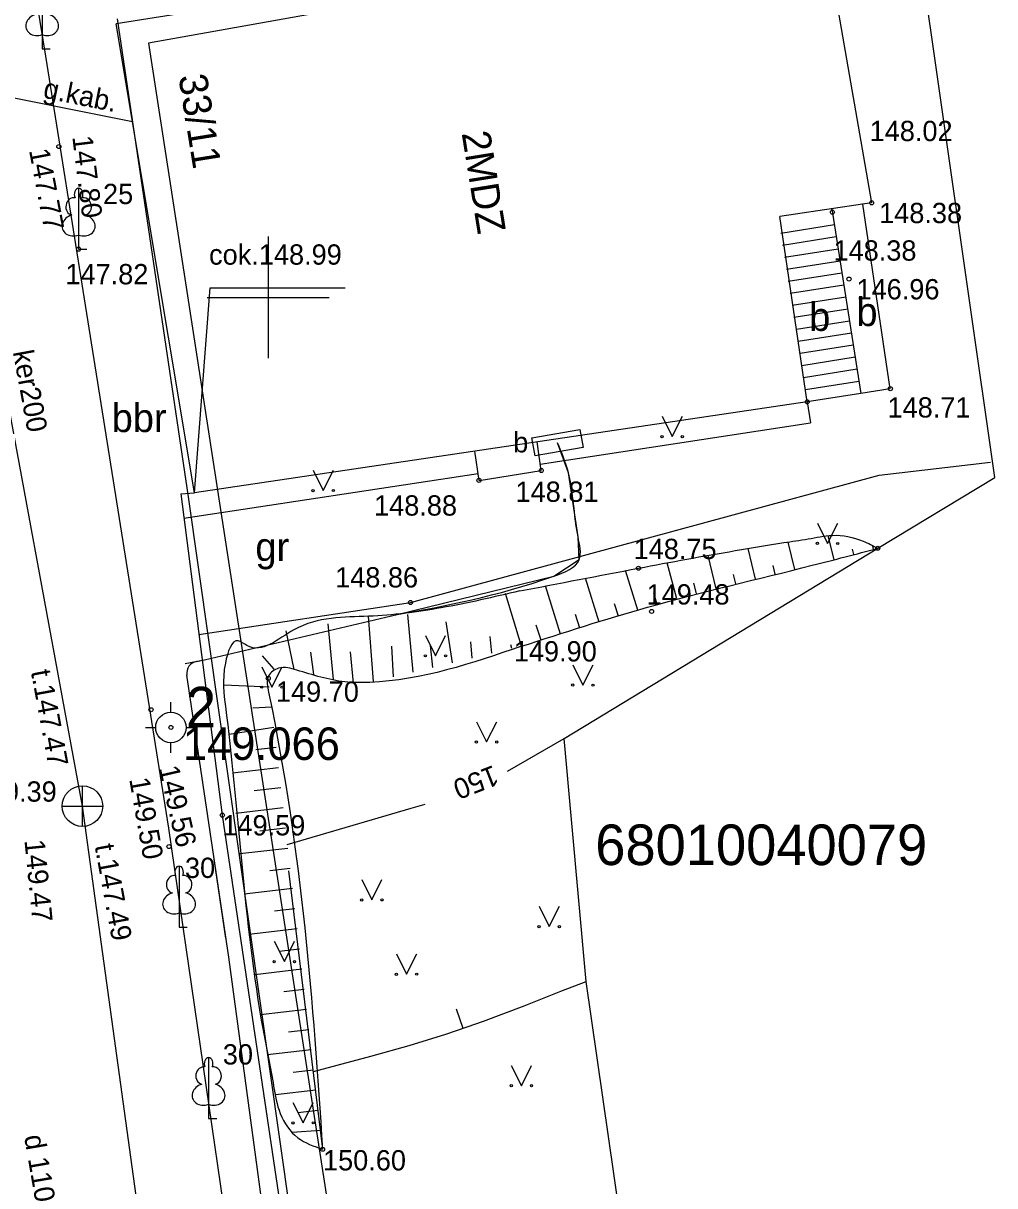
# Model space of a CAD drawing. Extents: x 728710 to 728960, y 272811 to 273475.
# Drawn here: x 728843.96 to 728867.91, y 272928.12 to 272956.75 of the extents above; entities that cross this region are included whole.
import ezdxf

# ---------------------------------------------------------------- set-up
doc = ezdxf.new("R2010")
doc.units = 0
for name, color, linetype in [('Level 10', 7, 'Continuous'), ('Level 12', 7, 'Continuous'), ('Level 15', 7, 'Continuous'), ('Level 23', 7, 'Continuous'), ('Level 29', 7, 'Continuous'), ('Level 3', 7, 'Continuous'), ('Level 30', 7, 'Continuous'), ('Level 34', 7, 'Continuous'), ('Level 36', 7, 'Continuous'), ('Level 4', 7, 'Continuous'), ('Level 48', 7, 'Continuous'), ('Level 50', 7, 'Continuous'), ('Level 51', 7, 'Continuous'), ('Level 55', 7, 'Continuous'), ('Level 56', 7, 'Continuous'), ('Level 57', 7, 'Continuous'), ('Level 58', 7, 'Continuous'), ('Level 59', 7, 'Continuous'), ('Level 6', 7, 'Continuous'), ('Level 60', 7, 'Continuous'), ('Level 62', 7, 'Continuous'), ('Level 63', 7, 'Continuous'), ('Level 9', 7, 'Continuous'), ('RAMI_UZMR_####_####_#', 7, 'Continuous'), ('RELJ_AATZ_####_TKST_#', 7, 'Continuous'), ('RELJ_NOGA_####_####_#', 7, 'Continuous'), ('ROBZ_ELEM_####_####_#', 7, 'Continuous'), ('ROBZ_KADS_####_TKST_#', 7, 'Continuous'), ('ROBZ_UZMR_####_####_#', 7, 'Continuous'), ('SAKT_VADV_PKAB_TKST_#', 7, 'Continuous'), ('TERT_ELEM_####_####_#', 7, 'Continuous'), ('TERT_KONT_####_####_#', 7, 'Continuous')]:
    doc.layers.add(name, color=color, linetype=linetype)

msp = doc.modelspace()

# ---------------------------------------------------------------- linework, layer by layer
at = {"layer": 'Level 10'}
for p, q in [((728850, 272951.5), (728850, 272950)), ((728848.5, 272950), (728850, 272950)), ((728850, 272950), (728850, 272948.5)), ((728850, 272950), (728851.5, 272950)), ((728847.603, 272939.781), (728847.603, 272940.031)), ((728846.978, 272939.406), (728847.228, 272939.406)), ((728847.978, 272939.406), (728848.228, 272939.406)), ((728847.603, 272938.781), (728847.603, 272939.031))]:
    msp.add_line(p, q, dxfattribs=at)
for radius in [0.375, 0.05]:
    msp.add_circle((728847.603, 272939.406), radius, dxfattribs=at)
at = {"layer": 'Level 12'}
for p, q in [((728862.984, 272943.296), (728862.82, 272943.972)), ((728863.954, 272943.541), (728863.802, 272944.123)), ((728864.922, 272943.793), (728864.899, 272943.881)), ((728861.041, 272942.825), (728860.842, 272943.643)), ((728862.013, 272943.061), (728861.83, 272943.814)), ((728864.438, 272943.667), (728864.403, 272943.801)), ((728859.113, 272942.294), (728858.811, 272943.269)), ((728860.073, 272942.575), (728859.837, 272943.462)), ((728862.498, 272943.179), (728862.446, 272943.394)), ((728858.158, 272941.998), (728857.823, 272943.08)), ((728861.527, 272942.943), (728861.469, 272943.178)), ((728856.247, 272941.407), (728855.846, 272942.702)), ((728857.202, 272941.703), (728856.835, 272942.891)), ((728859.591, 272942.439), (728859.509, 272942.717)), ((728860.556, 272942.703), (728860.488, 272942.958)), ((728858.635, 272942.146), (728858.54, 272942.455)), ((728852.599, 272940.537), (728852.477, 272942.144)), ((728853.572, 272940.769), (728853.44, 272942.19)), ((728857.68, 272941.851), (728857.575, 272942.191)), ((728851.612, 272940.588), (728851.479, 272941.96)), ((728854.545, 272941.001), (728854.39, 272942.006)), ((728856.725, 272941.555), (728856.609, 272941.927)), ((728850.642, 272940.831), (728850.447, 272941.788)), ((728855.517, 272941.233), (728855.473, 272941.65)), ((728851.128, 272940.713), (728851.054, 272941.261)), ((728852.104, 272940.5), (728852.029, 272941.272)), ((728853.086, 272940.653), (728853.05, 272941.41)), ((728854.058, 272940.885), (728854, 272941.421)), ((728855.031, 272941.117), (728854.997, 272941.519)), ((728856.004, 272941.349), (728855.983, 272941.444)), ((728850.148, 272940.839), (728849.862, 272941.169)), ((728850.024, 272940.402), (728848.911, 272940.447)), ((728850.081, 272939.905), (728849.626, 272939.878)), ((728850.139, 272939.408), (728849.036, 272939.236)), ((728850.196, 272938.912), (728849.699, 272938.854)), ((728850.254, 272938.415), (728849.118, 272938.283)), ((728850.311, 272937.918), (728849.659, 272937.843)), ((728850.369, 272937.422), (728849.206, 272937.287)), ((728850.426, 272936.925), (728849.797, 272936.852)), ((728850.484, 272936.428), (728849.302, 272936.291)), ((728850.541, 272935.931), (728850.044, 272935.874)), ((728850.599, 272935.435), (728849.408, 272935.297)), ((728850.656, 272934.938), (728850.159, 272934.881)), ((728850.714, 272934.441), (728849.527, 272934.304)), ((728850.771, 272933.945), (728850.274, 272933.887)), ((728850.829, 272933.448), (728849.669, 272933.314)), ((728850.886, 272932.951), (728850.389, 272932.894)), ((728850.944, 272932.455), (728849.813, 272932.324)), ((728851.001, 272931.958), (728850.504, 272931.901)), ((728851.059, 272931.461), (728849.985, 272931.337)), ((728851.116, 272930.965), (728850.62, 272930.907)), ((728851.174, 272930.468), (728850.18, 272930.353)), ((728851.231, 272929.971), (728850.735, 272929.914)), ((728851.289, 272929.475), (728850.595, 272929.424))]:
    msp.add_line(p, q, dxfattribs=at)
for points in [[(728856.247, 272941.407), (728859.353, 272942.368), (728863.411, 272943.4), (728865.025, 272943.82)], [(728856.247, 272941.407), (728852.507, 272940.515), (728851.889, 272940.53), (728850.706, 272940.818), (728850.259, 272940.864), (728850.011, 272940.679), (728850.011, 272940.273), (728851.342, 272929.014)]]:
    msp.add_spline(points, degree=3, dxfattribs=at)
at = {"layer": 'Level 15'}
msp.add_lwpolyline([(728856.5, 272946.539), (728857.683, 272946.744), (728857.76, 272946.301), (728856.577, 272946.096)], close=True, dxfattribs=at)
at = {"layer": 'Level 23'}
msp.add_lwpolyline([(728849.007, 272911.469), (728845.423, 272937.468), (728840.671, 272963.226)], dxfattribs=at)
at = {"layer": 'Level 29'}
for p, q in [((728845.423, 272936.968), (728845.423, 272937.968)), ((728844.923, 272937.468), (728845.923, 272937.468))]:
    msp.add_line(p, q, dxfattribs=at)
msp.add_circle((728845.423, 272937.468), 0.5, dxfattribs=at)
at = {"layer": 'Level 3'}
for p, q in [((728863.627, 272959.495), (728846.257, 272956.74)), ((728863.627, 272959.495), (728864.872, 272952.33)), ((728848.185, 272945.19), (728846.257, 272956.74)), ((728864.872, 272952.33), (728862.609, 272951.995)), ((728863.286, 272947.428), (728862.609, 272951.995)), ((728863.286, 272947.428), (728848.185, 272945.19))]:
    msp.add_line(p, q, dxfattribs=at)
at = {"layer": 'Level 30'}
for points in [[(728854.901, 272932.029), (728855.308, 272932.171), (728856.31, 272932.552), (728857.21, 272932.906), (728857.836, 272933.151)], [(728851.12, 272930.929), (728851.701, 272931.086), (728852.533, 272931.31), (728853.472, 272931.573), (728854.377, 272931.846), (728854.901, 272932.029)]]:
    msp.add_lwpolyline(points, dxfattribs=at)
at = {"layer": 'Level 34'}
for points in [[(728856.199, 272942.769), (728859.127, 272943.329), (728860.319, 272943.552), (728861.513, 272943.762), (728862.709, 272943.959), (728863.306, 272944.051), (728863.903, 272944.139), (728864.662, 272943.996), (728865.025, 272943.82)], [(728856.199, 272942.769), (728854.268, 272942.352), (728852.477, 272942.144), (728850.634, 272941.81), (728849.478, 272941.421), (728849.262, 272941.54), (728848.947, 272940.993), (728848.947, 272939.921), (728849.876, 272931.948), (728850.135, 272930.573), (728850.299, 272929.893), (728850.73, 272929.3), (728851.342, 272929.014)]]:
    msp.add_spline(points, degree=3, dxfattribs=at)
at = {"layer": 'Level 36'}
for points in [[(728847.955, 272940.979), (728848.43, 272941.072), (728853.176, 272942.187), (728857.037, 272943.133), (728857.668, 272943.54), (728857.638, 272944.102), (728857.402, 272945.676), (728857.13, 272946.42)], [(728848.959, 272934.212), (728848.67, 272936.162)]]:
    msp.add_lwpolyline(points, dxfattribs=at)
at = {"layer": 'Level 4'}
for p, q in [((728856.707, 272945.895), (728863.365, 272946.907)), ((728855.174, 272945.65), (728847.924, 272944.551)), ((728848.291, 272941.698), (728853.509, 272942.484))]:
    msp.add_line(p, q, dxfattribs=at)
for points in [[(728856.484, 272960.622), (728845.294, 272958.672), (728844.766, 272958.358), (728844.393, 272957.882), (728844.309, 272957.202), (728844.514, 272955.94), (728847.548, 272936.925), (728849.888, 272920.816), (728857.475, 272869.863), (728857.811, 272869.575)], [(728863.286, 272947.428), (728863.365, 272946.907)], [(728865.056, 272945.624), (728867.8, 272945.943)], [(728853.509, 272942.484), (728865.056, 272945.624)], [(728847.845, 272945.161), (728848.185, 272945.19)], [(728847.845, 272945.161), (728848.864, 272937.245), (728851.243, 272921.263), (728853.291, 272907.008)]]:
    msp.add_lwpolyline(points, dxfattribs=at)
at = {"layer": 'Level 48'}
for centre in [(728844.842, 272953.717), (728863.907, 272952.1), (728864.872, 272952.33), (728845.329, 272951.188), (728864.315, 272950.452), (728865.334, 272947.75), (728863.286, 272947.428), (728856.731, 272945.736), (728855.197, 272945.493), (728865.025, 272943.82), (728859.127, 272943.329), (728853.509, 272942.484), (728859.451, 272942.264), (728850.003, 272940.615), (728847.113, 272939.842), (728848.871, 272937.246), (728847.556, 272936.472), (728851.342, 272929.014)]:
    msp.add_circle(centre, 0.05, dxfattribs=at)
at = {"layer": 'Level 6'}
for p, q in [((728855.896, 272938.333), (728857.298, 272939.138)), ((728850.472, 272936.526), (728853.527, 272937.417)), ((728853.527, 272937.417), (728853.866, 272937.516)), ((728854.803, 272931.991), (728854.646, 272932.465))]:
    msp.add_line(p, q, dxfattribs=at)
at = {"layer": 'Level 9'}
for p, q in [((728863.894, 272952.185), (728864.609, 272947.636)), ((728865.334, 272947.75), (728864.66, 272952.299)), ((728863.286, 272947.428), (728862.609, 272951.995)), ((728863.957, 272951.785), (728862.634, 272951.577)), ((728864.003, 272951.489), (728862.68, 272951.281)), ((728864.05, 272951.192), (728862.727, 272950.984)), ((728864.096, 272950.896), (728862.773, 272950.688)), ((728864.143, 272950.6), (728862.82, 272950.392)), ((728864.19, 272950.303), (728862.867, 272950.095)), ((728864.236, 272950.007), (728862.913, 272949.799)), ((728864.283, 272949.711), (728862.96, 272949.503)), ((728864.329, 272949.414), (728863.022, 272949.209)), ((728864.376, 272949.118), (728863.066, 272948.912)), ((728864.422, 272948.821), (728863.11, 272948.615)), ((728864.469, 272948.525), (728863.154, 272948.318)), ((728864.516, 272948.229), (728863.198, 272948.022)), ((728864.562, 272947.932), (728863.242, 272947.725)), ((728864.609, 272947.636), (728863.286, 272947.428)), ((728865.334, 272947.75), (728864.609, 272947.636)), ((728856.731, 272945.736), (728856.627, 272946.441)), ((728855.197, 272945.493), (728855.09, 272946.213)), ((728855.197, 272945.493), (728856.731, 272945.736))]:
    msp.add_line(p, q, dxfattribs=at)
msp.add_lwpolyline([(728848.185, 272945.19), (728848.571, 272950.238), (728851.902, 272950.238)], dxfattribs=at)
at = {"layer": 'RAMI_UZMR_####_####_#'}
for points in [[(728862.157, 272893.095), (728861.3, 272900.225), (728860.555, 272913.018), (728859.353, 272922.664), (728857.836, 272933.151), (728857.298, 272939.138), (728865.025, 272943.82), (728867.908, 272945.567), (728865.999, 272958.94), (728863.367, 272971.714), (728860.682, 272977.116), (728851.003, 272976.08), (728851.179, 272982.093), (728851.003, 272989.484), (728862.411, 272996.126), (728865.099, 273006.046), (728863.87, 273011.218), (728860.116, 273016.786), (728848.126, 273018.981), (728842.745, 273067.512)], [(728846.661, 272954.322), (728808.413, 272961.978)]]:
    msp.add_lwpolyline(points, dxfattribs=at)
at = {"layer": 'RELJ_AATZ_####_TKST_#'}
msp.add_lwpolyline([(728850.504, 272935.873), (728851.342, 272929.014)], dxfattribs=at)
at = {"layer": 'ROBZ_ELEM_####_####_#'}
for points in [[(728865.859, 272959.623), (728847.05, 272956.265)], [(728847.05, 272956.265), (728859.497, 272875.667)]]:
    msp.add_lwpolyline(points, dxfattribs=at)
at = {"layer": 'ROBZ_UZMR_####_####_#'}
for p, q in [((728848.039, 272945.089), (728846.285, 272956.862)), ((728851.974, 272917.451), (728848.039, 272945.089))]:
    msp.add_line(p, q, dxfattribs=at)
at = {"layer": 'TERT_ELEM_####_####_#'}
for points in [[(728848.236, 272941.034), (728848.43, 272941.072), (728853.176, 272942.187)], [(728853.698, 272900.249), (728853.629, 272900.797), (728852.071, 272911.456), (728850.504, 272922.854), (728849.028, 272933.745), (728847.997, 272940.696)]]:
    msp.add_lwpolyline(points, dxfattribs=at)
msp.add_arc((728848.294, 272940.74), 0.3, 101.0778, 188.437, dxfattribs=at)
msp.add_spline([(728853.176, 272942.187), (728857.037, 272943.133), (728857.668, 272943.54), (728857.638, 272944.102), (728857.504, 272945.105), (728857.402, 272945.676), (728857.13, 272946.42)], degree=3, dxfattribs=at)
at = {"layer": 'TERT_KONT_####_####_#'}
for p, q in [((728844.431, 272956.474), (728844.431, 272956.127)), ((728844.431, 272956.127), (728844.631, 272956.127)), ((728845.329, 272951.535), (728845.329, 272951.188)), ((728845.329, 272951.188), (728845.529, 272951.188)), ((728859.708, 272947.071), (728859.958, 272946.571)), ((728859.958, 272946.571), (728860.208, 272947.071)), ((728851.109, 272945.743), (728851.359, 272945.243)), ((728851.359, 272945.243), (728851.609, 272945.743)), ((728863.537, 272944.439), (728863.787, 272943.939)), ((728863.787, 272943.939), (728864.037, 272944.439)), ((728853.875, 272941.671), (728854.125, 272941.171)), ((728854.125, 272941.171), (728854.375, 272941.671)), ((728849.843, 272940.9), (728850.093, 272940.4)), ((728850.093, 272940.4), (728850.343, 272940.9)), ((728857.507, 272940.949), (728857.757, 272940.449)), ((728857.757, 272940.449), (728858.007, 272940.949)), ((728855.135, 272939.548), (728855.385, 272939.048)), ((728855.385, 272939.048), (728855.635, 272939.548)), ((728852.305, 272935.658), (728852.555, 272935.158)), ((728852.555, 272935.158), (728852.805, 272935.658)), ((728856.678, 272935), (728856.928, 272934.5)), ((728856.928, 272934.5), (728857.178, 272935)), ((728847.806, 272934.837), (728847.806, 272934.49)), ((728847.806, 272934.49), (728848.006, 272934.49)), ((728850.149, 272934.137), (728850.399, 272933.637)), ((728850.399, 272933.637), (728850.649, 272934.137)), ((728853.163, 272933.827), (728853.413, 272933.327)), ((728853.413, 272933.327), (728853.663, 272933.827)), ((728855.992, 272931.081), (728856.242, 272930.581)), ((728856.242, 272930.581), (728856.492, 272931.081)), ((728848.532, 272930.122), (728848.532, 272929.775)), ((728850.61, 272930.164), (728850.86, 272929.664)), ((728850.86, 272929.664), (728851.11, 272930.164)), ((728848.532, 272929.775), (728848.732, 272929.775))]:
    msp.add_line(p, q, dxfattribs=at)
for points in [[(728844.431, 272957.627), (728844.431, 272956.474)], [(728845.329, 272952.688), (728845.329, 272951.535)], [(728845.419, 272952.456), (728845.418, 272952.457)], [(728847.806, 272935.99), (728847.806, 272934.837)], [(728847.896, 272935.758), (728847.895, 272935.759)], [(728848.532, 272931.275), (728848.532, 272930.122)], [(728848.622, 272931.043), (728848.621, 272931.044)]]:
    msp.add_lwpolyline(points, dxfattribs=at)
for centre, radius in [((728859.707, 272946.57), 0.028), ((728860.207, 272946.57), 0.0263), ((728851.108, 272945.242), 0.028), ((728851.608, 272945.242), 0.0263), ((728863.537, 272943.939), 0.028), ((728864.037, 272943.939), 0.0263), ((728853.875, 272941.171), 0.028), ((728854.375, 272941.171), 0.0263), ((728849.843, 272940.399), 0.028), ((728850.343, 272940.399), 0.0263), ((728857.507, 272940.449), 0.028), ((728858.007, 272940.449), 0.0263), ((728855.134, 272939.047), 0.028), ((728855.634, 272939.047), 0.0263), ((728852.305, 272935.157), 0.028), ((728852.805, 272935.157), 0.0263), ((728856.678, 272934.499), 0.028), ((728857.178, 272934.499), 0.0263), ((728850.149, 272933.637), 0.028), ((728850.649, 272933.637), 0.0263), ((728853.162, 272933.327), 0.028), ((728853.662, 272933.327), 0.0263), ((728855.992, 272930.581), 0.028), ((728856.492, 272930.581), 0.0263), ((728850.61, 272929.664), 0.028), ((728851.11, 272929.664), 0.0263)]:
    msp.add_circle(centre, radius, dxfattribs=at)
for centre, major_axis, ratio, start_param, end_param in [((728844.341, 272956.72), (0.307, 0.095), 0.814445, 1.570796, 4.752015), ((728844.52, 272956.72), (-0.307, 0.095), 0.814445, 1.531171, 4.712389), ((728845.201, 272952.243), (-0.039, -0.212), 0.861323, 3.141593, 6.283185), ((728845.329, 272952.538), (0, -0.15), 0.707107, 3.14537, 5.287485), ((728845.329, 272952.538), (0, -0.15), 0.707107, 0.995701, 3.137816), ((728845.457, 272952.243), (0.039, -0.212), 0.861323, 0, 3.141593), ((728845.239, 272951.781), (0.307, 0.095), 0.814445, 1.570796, 4.752015), ((728845.419, 272951.781), (-0.307, 0.095), 0.814445, 1.531171, 4.712389), ((728847.806, 272935.84), (0, -0.15), 0.707107, 3.14537, 5.287485), ((728847.806, 272935.84), (0, -0.15), 0.707107, 0.995701, 3.137816), ((728847.678, 272935.545), (-0.039, -0.212), 0.861323, 3.141593, 6.283185), ((728847.934, 272935.545), (0.039, -0.212), 0.861323, 0, 3.141593), ((728847.716, 272935.083), (0.307, 0.095), 0.814445, 1.570796, 4.752015), ((728847.896, 272935.083), (-0.307, 0.095), 0.814445, 1.531171, 4.712389), ((728848.532, 272931.125), (0, -0.15), 0.707107, 3.14537, 5.287485), ((728848.532, 272931.125), (0, -0.15), 0.707107, 0.995701, 3.137816), ((728848.404, 272930.83), (-0.039, -0.212), 0.861323, 3.141593, 6.283185), ((728848.66, 272930.83), (0.039, -0.212), 0.861323, 0, 3.141593), ((728848.442, 272930.368), (0.307, 0.095), 0.814445, 1.570796, 4.752015), ((728848.622, 272930.368), (-0.307, 0.095), 0.814445, 1.531171, 4.712389)]:
    msp.add_ellipse(centre, major_axis=major_axis, ratio=ratio, start_param=start_param, end_param=end_param, dxfattribs=at)

# ---------------------------------------------------------------- texts
at = {"layer": 'Level 50'}
for s, p in [('cok.148.99', (728848.544, 272950.807)), ('b', (728856.04, 272946.181))]:
    msp.add_text(s, height=0.5, dxfattribs=at).set_placement(p)
at = {"layer": 'Level 51'}
msp.add_text('150', height=0.5, rotation=201.292, dxfattribs=at).set_placement((728855.552, 272938.487))
at = {"layer": 'Level 55'}
msp.add_text('d 110', height=0.5, rotation=279.7905, dxfattribs=at).set_placement((728843.984, 272929.332))
at = {"layer": 'Level 56'}
msp.add_text(' 149.39', height=0.5, dxfattribs=at).set_placement((728842.56, 272937.578))
at = {"layer": 'Level 57'}
for s, p in [(' 148.02', (728864.638, 272953.851)), (' 148.38', (728864.872, 272951.83)), (' 148.38', (728863.748, 272950.906)), (' 147.82', (728844.818, 272950.323)), (' 146.96', (728864.315, 272949.952)), (' 148.71', (728865.079, 272947.041)), (' 148.81', (728855.911, 272944.964)), (' 148.88', (728852.425, 272944.625)), (' 148.75', (728858.822, 272943.554)), (' 148.86', (728851.465, 272942.854)), (' 149.48', (728859.141, 272942.434)), (' 149.90', (728855.869, 272941.032)), (' 149.70', (728850.006, 272940.039)), ('149.59', (728848.871, 272936.746)), (' 150.60', (728851.166, 272928.493))]:
    msp.add_text(s, height=0.5, dxfattribs=at).set_placement(p)
for s, rotation, p in [('147.80', 277.0471, (728845.172, 272953.958)), ('147.77', 280.7448, (728844.105, 272953.624)), ('149.56', 282.8617, (728847.301, 272938.411)), ('149.50', 280.0353, (728846.574, 272938.135)), ('149.47', 275.6277, (728843.993, 272936.624))]:
    msp.add_text(s, height=0.5, rotation=rotation, dxfattribs=at).set_placement(p)
at = {"layer": 'Level 58'}
for s, p in [('b', (728863.333, 272949.175)), ('b', (728864.498, 272949.296)), ('bbr', (728846.144, 272946.683)), ('gr', (728849.686, 272943.507))]:
    msp.add_text(s, height=0.7, dxfattribs=at).set_placement(p)
at = {"layer": 'Level 59'}
msp.add_text('2MDZ', height=0.7, rotation=279.118, dxfattribs=at).set_placement((728854.768, 272954.048))
at = {"layer": 'Level 60'}
for s, p in [('ker200', (728843.706, 272948.658)), ('t.147.47', (728844.151, 272940.785)), ('t.147.49', (728845.721, 272936.492))]:
    msp.add_text(s, height=0.5, rotation=280.453, dxfattribs=at).set_placement(p)
at = {"layer": 'Level 62'}
msp.add_text('33/11', height=0.7, rotation=279.118, dxfattribs=at).set_placement((728847.787, 272955.451))
at = {"layer": 'Level 63'}
for s, height, p in [(' 2', 1, (728847.603, 272939.406)), (' 149.066', 0.8, (728847.603, 272938.606))]:
    msp.add_text(s, height=height, dxfattribs=at).set_placement(p)
at = {"layer": 'RELJ_NOGA_####_####_#'}
for s, p in [('25', (728845.931, 272952.299)), ('30', (728847.95, 272935.698)), ('30', (728848.883, 272931.103))]:
    msp.add_text(s, height=0.5, dxfattribs=at).set_placement(p)
at = {"layer": 'ROBZ_KADS_####_TKST_#'}
msp.add_text('68010040079', height=1, dxfattribs=at).set_placement((728858.062, 272936.015))
at = {"layer": 'SAKT_VADV_PKAB_TKST_#'}
msp.add_text('g.kab.', height=0.5, rotation=348.6811, dxfattribs=at).set_placement((728844.433, 272954.921))

doc.saveas('drawing.dxf')
